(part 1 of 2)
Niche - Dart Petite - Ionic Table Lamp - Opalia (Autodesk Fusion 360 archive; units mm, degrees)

design "Marble Base - Ionic Table Lamp - Ketra Ready - 120V - Opalia Collection" references "Trove - TL", "Arca Tall", "Marble Base - Ionic Table Lamp - Ketra Ready - 120V", "Chinois", "Facet Petite", "Ketra - A20 Tunable Lamp", "Arca Petite", "Orb 8.5In - Solitaire Petite", "Dart Petite", "Dart"
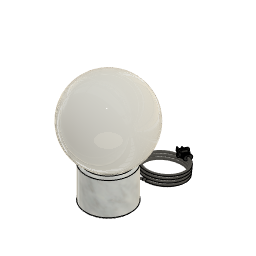
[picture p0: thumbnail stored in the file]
component_insert "Component Insert2"
component_insert "Component Insert3"
component_insert "Component Insert4"
component_insert "Component Insert5"
position "Position1"
component_insert "Component Insert6"
component_insert "Component Insert7"
component_insert "Component Insert8"
external_derived "ExternalDerived1" bodies "Orb-8.5"
derived_instance "DerivedInstance1"
position "Position2"
external_derived "ExternalDerived2" bodies "Dart Grand"
derived_instance "DerivedInstance2"
offset_faces "OffsetFaces1" distance -10.16
position "Position3"
external_derived "ExternalDerived3" bodies "Dart Petite"
derived_instance "DerivedInstance3"
offset_faces "OffsetFaces1" distance -10.16
position "Position4"
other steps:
derived_base_feature "Derived Base Feature1" bodies "Dart Grand"
derived_base_feature "Derived Base Feature1" bodies "Dart Petite"
derived_base_feature "Derived Base Feature1" bodies "Orb-8.5"
create_component "CreateComponent1"
create_component "CreateComponent2"
create_component "CreateComponent3"
named bodies: "Orb-8.5", "Dart Grand", "Dart Petite"

design "Dart Petite"
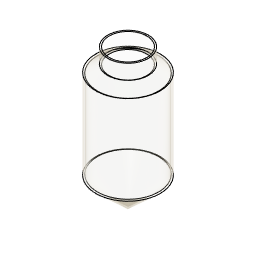
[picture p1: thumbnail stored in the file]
sketch "Sketch1" plane through (0, 0, 0) normal (0, 0, 1) x axis (1, 0, 0)
work_plane "WorkPlane1" AlongDistance 76.2
sketch "Sketch2" plane through (0, 0, 76.2) normal (0, 0, 1) x axis (1, 0, 0)
sketch "Sketch3" plane through (0, 0, 76.2) normal (0, 0, 1) x axis (1, 0, 0)
sketch "Sketch4" plane through (0, 0, 76.2) normal (0, 0, 1) x axis (1, 0, 0)
  circle C1 centre (0, 0) radius 82.55
  point P1 (0, 0)
  point P2 (0, 0)
  coincident P1 P2
  dimension "d2" diameter C1 = 165.1
loft "Loft1" sketch "Sketch4" bodies "Dart Petite"
extrude "Extrude1" add of existing geometry blind 228.6
work_plane "WorkPlane2" AlongDistance 19.05
sketch "Sketch5" plane through (0, 0, 323.85) normal (0, 0, 1) x axis (1, 0, 0)
  circle C1 centre (0, 0) radius 52.07
  point P1 (0, 0)
  point P2 (0, 0)
  coincident P1 P2
  dimension "d6" diameter C1 = 104.14
loft "Loft2" sketch "Sketch5"
extrude "Extrude2" add of existing geometry blind 38.1
shell "Shell3" innerThickness 3.81
component_from_bodies "Body->Comp"
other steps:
base_feature "Base Feature" bodies "Dart Petite"
create_component "CreateComponent1"
remove_body "RemoveBody1"
named bodies: "Dart Petite"

design "Marble Base - Ionic Table Lamp - Ketra Ready - 120V" references "Marble Base - Ionic Table Lamp - 120V"
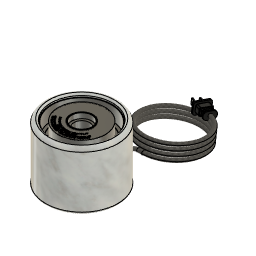
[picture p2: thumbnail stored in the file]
external_derived "ExternalDerived1" bodies "Coiled - SVT (Blk Fabric)", "Body1", "Marble Base", "Body2", "Silicone Gasket", "Plastic Insert"
derived_instance "DerivedInstance1"
derived_instance "DerivedInstance2"
derived_instance "DerivedInstance3"
derived_instance "DerivedInstance4"
derived_instance "DerivedInstance5"
derived_instance "DerivedInstance6"
derived_instance "DerivedInstance7"
derived_instance "DerivedInstance8"
derived_instance "DerivedInstance9"
derived_instance "DerivedInstance10"
derived_instance "DerivedInstance11"
derived_instance "DerivedInstance12"
offset_faces "OffsetFaces1" distance 3.81
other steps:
derived_base_feature "Derived Base Feature1" bodies "Rubber Grommet"
derived_base_feature "Derived Base Feature1" bodies "Neoprene Pad"
derived_base_feature "Derived Base Feature1" bodies "2-Pole Plug End"
derived_base_feature "Derived Base Feature1" bodies "Body1"
derived_base_feature "Derived Base Feature1" bodies "Body1", "Body2"
derived_base_feature "Derived Base Feature1" bodies "Body1"
derived_base_feature "Derived Base Feature1" bodies "Silicone Gasket"
derived_base_feature "Derived Base Feature1" bodies "Plastic Insert"
derived_base_feature "Derived Base Feature1" bodies "Body1"
derived_base_feature "Derived Base Feature1" bodies "Body1"
derived_base_feature "Derived Base Feature1" bodies "Coiled - SVT (Blk Fabric)"
derived_base_feature "Derived Base Feature1" bodies "Marble Base"
create_component "CreateComponent1"
create_component "CreateComponent2"
create_component "CreateComponent3"
create_component "CreateComponent4"
create_component "CreateComponent5"
create_component "CreateComponent6"
create_component "CreateComponent7"
create_component "CreateComponent8"
create_component "CreateComponent9"
create_component "CreateComponent10"
create_component "CreateComponent11"
create_component "CreateComponent12"
named bodies: "Coiled - SVT (Blk Fabric)", "Marble Base", "Body1", "Body2", "Plastic Insert", "Silicone Gasket", "Neoprene Pad", "2-Pole Plug End", "Rubber Grommet"

design "Arca Petite"
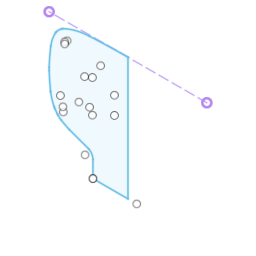
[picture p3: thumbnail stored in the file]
sketch "Sketch1" plane through (0, 0, 0) normal (0, 1, 0) x axis (1, 0, 0)
  line L1 (0, 101.6) -> (0, -101.6)
  line L2 (127, 0) -> (-127, 0)
  line L3 (63.5, 101.6) -> (-63.5, 101.6)
  perpendicular L1 L2
  parallel L2 L3
sketch "Sketch2" plane through (0, 0, 0) normal (0, 1, 0) x axis (1, 0, 0)
  line L1 (0, 101.6) -> (0, -101.6)
  line L2 (0, -76.2) -> (0, 101.6)
  line L3 (127, 0) -> (-127, 0)
  line L4 (114.3, 0) -> (-114.3, 0)
  line L5 (50.8, 101.6) -> (50.8, 63.5)
  line L6 (-50.8, 101.6) -> (50.8, 101.6)
  line L7 (-50.8, 63.5) -> (-50.8, 101.6)
  line L8 (63.5, 101.6) -> (-63.5, 101.6)
  line L9 (114.3, -76.2) -> (114.3, 63.5)
  line L10 (-114.3, -76.2) -> (114.3, -76.2)
  line L11 (-114.3, 63.5) -> (-114.3, -76.2)
  line L12 (-50.8, 63.5) -> (-114.3, 63.5)
  line L13 (114.3, 63.5) -> (50.8, 63.5)
  point P2 (0, 101.6)
  point P5 (0, 101.6)
  point P6 (0, -76.2)
  point P9 (-114.3, 0)
  point P10 (114.3, 0)
  point P11 (50.8, 101.6)
  point P19 (50.8, 63.5)
  coincident P2 P5
  coincident L1 P6
  coincident L3 P9
  coincident L3 P10
  vertical L5
  horizontal L6
  vertical L7
  coincident P11 L8
  horizontal L12
  vertical L9
  horizontal L10
  vertical L11
  coincident P19 L12
  collinear L12 L13
derived_base_feature "Derived Base Feature"
revolve "Revolve1" sketch "Sketch4" AlongAngle 360 bodies "Arca Petite"
shell "Shell1" innerThickness 3.81
component_from_bodies "Body->Comp"
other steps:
base_feature "Base Feature" bodies "Arca Petite"
create_component "CreateComponent1"
remove_body "RemoveBody1"
named bodies: "Arca Petite"

design "Neoprene Pad"
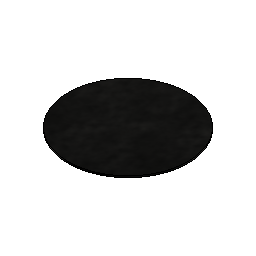
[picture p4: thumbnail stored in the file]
sketch "Sketch1" plane through (0, 0, 0) normal (0, 0, 1) x axis (1, 0, 0)
  circle C1 centre (0, 0) radius 57.15
  point P1 (0, 0)
  point P2 (0, 0)
  coincident P1 P2
extrude "Extrude1" new body sketch "Sketch1" along normal blind 1.5875 bodies "Neoprene Pad"
component_from_bodies "Body->Comp"
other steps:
base_feature "Base Feature" bodies "Neoprene Pad"
create_component "CreateComponent1"
remove_body "RemoveBody1"
named bodies: "Neoprene Pad"

design "T9 - Bulb"
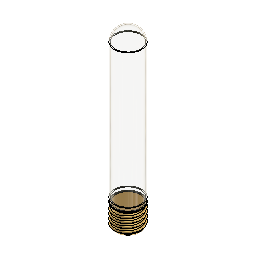
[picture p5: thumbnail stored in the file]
sketch "Sketch1" plane through (0, 0, 0) normal (0, 1, 0) x axis (1, 0, 0)
  line L1 (0, -166.37) -> (0, 0)
  line L2 (13.97, -13.97) -> (13.97, -152.4)
  line L3 (-13.97, -152.4) -> (-13.97, -13.97)
  line L4 (0, 0) -> (0, -166.37)
  line L5 (12.97, -13.97) -> (12.97, -152.4)
  line L6 (-12.97, -152.4) -> (-12.97, -13.97)
  line L7 (-12.3978, -10.16) -> (-13.4404, -10.16)
  line L8 (13.4404, -10.16) -> (12.3978, -10.16)
  arc A1 centre (0, -152.4) radius 13.97 clockwise from (13.97, -152.4) to (-13.97, -152.4)
  arc A2 centre (0, -152.4) radius 12.97 clockwise from (12.97, -152.4) to (-12.97, -152.4)
  arc A3 centre (0, -13.97) radius 13.97 clockwise from (13.4404, -10.16) to (13.97, -13.97)
  arc A4 centre (0, -13.97) radius 13.97 clockwise from (-13.97, -13.97) to (-13.4404, -10.16)
  arc A5 centre (0, -13.97) radius 12.97 clockwise from (12.3978, -10.16) to (12.97, -13.97)
  arc A6 centre (0, -13.97) radius 12.97 clockwise from (-12.97, -13.97) to (-12.3978, -10.16)
  point P1 (0, 0)
  point P2 (0, 0)
  point P3 (0, -166.37)
  point P10 (0, 0)
  point P17 (13.4404, -10.16)
  point P19 (12.3978, -10.16)
  point P4 (13.97, -152.4)
  point P5 (13.97, -13.97)
  coincident P1 P2
  vertical L1
  tangent L2 A3
  tangent L3 A3
  parallel L2 L3
  tangent L3 A1
  tangent L2 A1
  midpoint P3 A1
  coincident P1 P10
  perpendicular L1 L7
  coincident P17 L7
  concentric A3 A4
  coincident P10 A3
  concentric A1 A2
  tangent L5 A2
  tangent L5 A5
  tangent L6 A5
  tangent L6 A2
  coincident P19 L7
  concentric A5 A6
  collinear L7 L8
  dimension "d6" distance L2 L3 = 27.94
  dimension "d7" distance P4 P5 = 138.43
revolve "Revolve1" sketch "Sketch1" AlongAngle 360 bodies "T9"
derived_base_feature "Derived Base Feature" bodies "E26 Base"
align "Align1"
move "Move1"
component_from_bodies "Body->Comp1"
component_from_bodies "Body->Comp2"
copy_paste "CutPaste1"
copy_paste "CutPaste2"
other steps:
base_feature "Base Feature1" bodies "T9"
base_feature "Base Feature1" bodies "E26 Base"
create_component "CreateComponent1"
create_component "CreateComponent2"
remove_body "RemoveBody1"
create_component "CreateComponent3"
remove_body "RemoveBody2"
remove_instance "RemoveInstance1"
remove_instance "RemoveInstance2"
named bodies: "T9", "E26 Base"

design "Facet Petite"
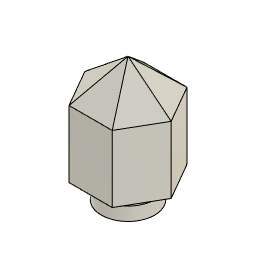
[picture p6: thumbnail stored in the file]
sketch "Sketch7" plane through (0, 0, 0) normal (1, 0, 0) x axis (0, 1, 0)
sketch "Sketch8" plane through (0, 0, 0) normal (0, 0, 1) x axis (1, 0, 0)
  circle C1 centre (0, 0) radius 50.8
  point P1 (0, 0)
  point P2 (0, 0)
  coincident P1 P2
  dimension "d17" diameter C1 = 101.6
extrude "Extrude5" new body sketch "Sketch8" along normal blind 25.4 and against normal blind 25.4
work_plane "WorkPlane1" AlongDistance 17.78
sketch "Sketch10" plane through (0, 0, 25.4) normal (0, 0, 1) x axis (-1, 0, 0)
  circle C1 centre (0, 0) radius 50.8
sketch "Sketch12" plane through (0, 0, 43.18) normal (0, 0, 1) x axis (1, 0, 0)
  line L1 (-82.1223, 0) -> (-41.0612, 71.12)
  line L2 (-41.0612, -71.12) -> (-82.1223, 0)
  line L3 (41.0612, -71.12) -> (-41.0612, -71.12)
  line L4 (82.1223, 0) -> (41.0612, -71.12)
  line L5 (41.0612, 71.12) -> (82.1223, 0)
  line L6 (-41.0612, 71.12) -> (41.0612, 71.12)
  point P1 (0, 0)
  point P8 (0, 0)
  coincident P1 P8
  dimension "d22" distance P8 L6 = 71.12
sketch "Sketch15" plane through (0, 0, 0) normal (0, 1, 0) x axis (1, 0, 0)
  line L1 (53.7365, -21.6801) -> (82.1223, -43.18)
  line L2 (-50.8, -25.4) -> (-82.1223, -43.18)
  point P2 (82.1223, -43.18)
  point P3 (82.1223, -43.18)
  point P5 (-82.1223, -43.18)
  point P7 (-82.1223, -43.18)
  point P6 (-50.8, -25.4)
  point P8 (-50.8, -25.4)
  coincident P2 P3
  coincident P5 P7
  coincident P6 P8
sketch "Sketch17" plane through (0, 0, 25.4) normal (0, 0, 1) x axis (-1, 0, 0)
  line L1 (51.3255, 0) -> (0, 0)
  line L2 (73.3235, 0) -> (0, 0)
  line L3 (-41.0612, -71.12) -> (-25.4, -43.9941)
  line L4 (-36.6617, -63.5) -> (-25.4, -43.9941)
  line L5 (78.4305, 0) -> (0, 0)
  line L6 (41.0612, -71.12) -> (25.4, -43.9941)
  line L7 (25.4, 43.9941) -> (41.0612, 71.12)
  line L8 (73.3235, 0) -> (0, 0)
  line L9 (-25.4, 43.9941) -> (-41.0612, 71.12)
  line L10 (0, 0) -> (0, 0)
  circle C1 centre (0, 0) radius 50.8
  point P1 (0, 0)
  point P4 (0, 0)
  point P2 (-41.0612, -71.12)
  point P6 (-41.0612, -71.12)
  point P3 (0, 0)
  point P7 (0, 0)
  point P9 (-25.4, -43.9941)
  point P12 (41.0612, -71.12)
  point P13 (41.0612, -71.12)
  point P15 (25.4, -43.9941)
  point P16 (41.0612, 71.12)
  point P17 (41.0612, 71.12)
  point P18 (25.4, 43.9941)
  point P19 (-41.0612, 71.12)
  point P20 (-41.0612, 71.12)
  point P21 (0, 0)
  point P23 (-25.4, 43.9941)
  point P25 (0, 0)
  point P24 (0, 0)
  point P26 (0, 0)
  horizontal L1
  coincident P1 P4
  coincident P2 P6
  horizontal L2
  coincident P3 P7
  coincident C1 P9
  coincident P12 P13
  horizontal L5
  coincident C1 P15
  coincident P16 P17
  coincident C1 P18
  coincident P19 P20
  horizontal L8
  coincident P1 P21
  coincident C1 P23
  coincident P1 P25
  coincident P24 P26
extrude "Extrude6" new body sketch "Sketch12" along normal blind 127
work_plane "WorkPlane2" AlongDistance 66.04
sketch "Sketch18" plane through (0, 0, 236.22) normal (0, 0, 1) x axis (1, 0, 0)
  line L1 (41.0612, -71.12) -> (0, 0)
  line L2 (82.1223, 0) -> (0, 0)
  line L3 (41.0612, 71.12) -> (0, 0)
  line L4 (-41.0612, 71.12) -> (0, 0)
  line L5 (-82.1223, 0) -> (0, 0)
  line L6 (-41.0612, -71.12) -> (0, 0)
  point P1 (0, 0)
  point P3 (0, 0)
  point P2 (41.0612, -71.12)
  point P4 (41.0612, -71.12)
  point P6 (0, 0)
  point P5 (82.1223, 0)
  point P7 (82.1223, 0)
  point P9 (0, 0)
  point P8 (41.0612, 71.12)
  point P10 (41.0612, 71.12)
  point P12 (0, 0)
  point P11 (-41.0612, 71.12)
  point P13 (-41.0612, 71.12)
  point P15 (0, 0)
  point P14 (-82.1223, 0)
  point P16 (-82.1223, 0)
  point P18 (0, 0)
  point P17 (-41.0612, -71.12)
  point P19 (-41.0612, -71.12)
  coincident P1 P3
  coincident P2 P4
  coincident P1 P6
  coincident P5 P7
  coincident P1 P9
  coincident P8 P10
  coincident P1 P12
  coincident P11 P13
  coincident P1 P15
  coincident P14 P16
  coincident P1 P18
  coincident P17 P19
loft "Loft1"
loft "Loft2" sketch "Sketch17"
component_from_bodies "Body->Comp"
extrude "Extrude1" cut of existing geometry blind -25.4
shell "Shell2" innerThickness 3.81
fillet "Fillet1" radius 7.62
fillet "Fillet2" radius 6.35
fillet "Fillet3" radius 6.35
fillet "Fillet4" radius 6.35
fillet "Fillet5" radius 6.35
fillet "Fillet6" radius 6.35
fillet "Fillet7" radius 3.81
fillet "Fillet8" radius 6.35
fillet "Fillet9" radius 6.35
fillet "Fillet10" radius 6.35
fillet "Fillet11" radius 6.35
fillet "Fillet12" radius 6.35
fillet "Fillet13" radius 2.286
shell "Shell1" innerThickness 2.54
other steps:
base_feature "Base Feature"
create_component "CreateComponent3"
remove_body "RemoveBody2"

design "Marble Base - Ionic Table Lamp - 120V" references "Dart", "Rubber Grommet", "Marble Base - Plastic Insert", "Chinois", "2-Pole Plug End", "Neoprene Pad", "Marble Base - Silicone Gasket", "Trove - TL", "Dart Petite", "Balon v2", "T9 - Bulb", "Orb 8.5In - Solitaire Petite", "T9-5In", "T8 LED 11", "Arca Tall", "Facet Petite"
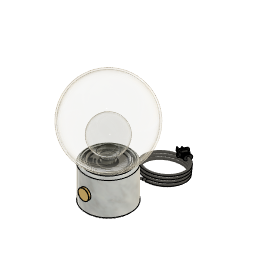
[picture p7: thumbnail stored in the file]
sketch "Sketch1" plane through (0, 0, 0) normal (0, 0, 1) x axis (1, 0, 0)
  circle C1 centre (0, 0) radius 63.5
  point P1 (0, 0)
  point P2 (0, 0)
  coincident P1 P2
extrude "Extrude1" new body sketch "Sketch1" along normal blind 101.6 bodies "Marble Base"
sketch "Sketch2" plane through (0, 0, 101.6) normal (0, 0, 1) x axis (-1, 0, 0)
  circle C1 centre (0, 0) radius 63.5
  circle C2 centre (0, 0) radius 53.975
  concentric C1 C2
  dimension "d3" diameter C2 = 107.95
extrude "Extrude2" cut sketch "Sketch2" profile of C2 against normal blind 34.925
sketch "Sketch3" plane through (0, 0, 66.675) normal (0, 0, 1) x axis (-1, 0, 0)
  circle C1 centre (0, 0) radius 53.975
  circle C2 centre (0, 0) radius 49.276
  point P1 (0, 0)
  point P3 (0, 0)
  coincident P1 P3
  dimension "d6" diameter C2 = 98.552
extrude "Extrude3" cut sketch "Sketch3" profile of C2 against normal blind 45.72
sketch "Sketch4" plane through (0, 0, 0) normal (0, 1, 0) x axis (1, 0, 0)
  circle C1 centre (0, -50.8) radius 3.81
  dimension "d9" diameter C1 = 7.62
extrude "Extrude4" cut sketch "Sketch4" against normal blind 127
sketch "Sketch5" plane through (0, 0, 0) normal (0, 1, 0) x axis (1, 0, 0)
  line L1 (0, -25.4) -> (0, 0)
  line L2 (0, -30.48) -> (0, -25.4)
  circle C1 centre (0, -30.48) radius 5.08
  point P1 (0, 0)
  point P2 (0, 0)
  point P4 (0, -30.48)
  point P5 (0, -30.48)
  coincident P1 P2
  vertical L1
  parallel L1 L2
  coincident P4 P5
  dimension "d12" diameter C1 = 10.16
extrude "Extrude5" cut sketch "Sketch5" profile of C1 along normal blind 114.3
fillet "Fillet1" radius 6.35 3.175 4.064
derived_base_feature "Derived Base Feature1" bodies "Rotary Switch"
derived_base_feature "Derived Base Feature1" bodies "Coiled - SVT (Blk Fabric)"
derived_base_feature "Derived Base Feature1" bodies "Glass Globe"
derived_base_feature "Derived Base Feature1" bodies "Metal Housing"
derived_base_feature "Derived Base Feature1" bodies "Metal Socket Cover"
derived_base_feature "Derived Base Feature1" bodies "Porcelain Socket"
derived_base_feature "Derived Base Feature1" bodies "Brass Dial - Dimmer Knob"
component_from_bodies "Body->Comp1"
offset_faces "OffsetFaces1" distance 12.7
offset_faces "OffsetFaces2" distance -12.7
derived_base_feature "Derived Base Feature1" bodies "Solitaire Petite"
move "Move1"
offset_faces "OffsetFaces1" distance 20.32
move "Move2"
extrude "Extrude6" add of existing geometry blind 25.4
offset_faces "OffsetFaces2" distance -3.81
fillet "Fillet2" radius 2.54
move "Move3"
derived_base_feature "Derived Base Feature2" bodies "Facet Petite"
move "Move4"
offset_faces "OffsetFaces1" distance 2.54
move "Move1"
derived_base_feature "Derived Base Feature1" bodies "Body1"
derived_base_feature "Derived Base Feature1" bodies "Body1"
derived_base_feature "Derived Base Feature1" bodies "Body1"
derived_base_feature "Derived Base Feature1" bodies "Body1"
derived_base_feature "Derived Base Feature1" bodies "Body1"
derived_base_feature "Derived Base Feature1" bodies "Body1", "Body2"
derived_base_feature "Derived Base Feature1" bodies "Body1"
position "Position1"
external_derived "ExternalDerived5" bodies "Plastic Insert"
derived_instance "DerivedInstance15"
offset_faces "OffsetFaces1" distance 3.81
offset_faces "OffsetFaces2" distance -1.0414
move "Move6"
external_derived "ExternalDerived6" sketch "Sketch3" bodies "Silicone Gasket"
derived_instance "DerivedInstance16"
offset_faces "OffsetFaces3" distance -10.795
move "Move1"
move_face "MoveFace1"
position "Position2"
position "Position3"
position "Position4"
position "Position5"
move "Move2"
position "Position6"
offset_faces "OffsetFaces2" distance -7.62
chamfer "Chamfer1" distance 0.381
remove_instance "RemoveInstance1"
remove_instance "RemoveInstance2"
remove_instance "RemoveInstance3"
remove_instance "RemoveInstance4"
move "Move1"
derived_base_feature "Derived Base Feature5" bodies "Oculo Petite"
align "Align1"
external_derived "ExternalDerived8"
derived_base_feature "Derived Base Feature7" bodies "Balon v2"
derived_base_feature "Derived Base Feature8" bodies "Balon v3"
align "Align3"
align "Align4"
external_derived "ExternalDerived10"
component_insert "Component Insert1"
position "Position7"
position "Position8"
derived_base_feature "Derived Base Feature11" bodies "Trove - TL"
move "Move10"
move "Move11"
remove_instance "RemoveInstance5"
split "Split1" bodies "Trove - TL (1)"
remove_body "RemoveBody2"
remove_body "RemoveBody3"
external_derived "ExternalDerived13" bodies "Trove - TL"
derived_instance "DerivedInstance20"
remove_body "RemoveBody4"
remove_body "RemoveBody5"
component_insert "Component Insert2"
component_insert "Component Insert3"
component_from_bodies "Body->Comp2"
remove_body "RemoveBody7"
move "Move12"
move "Move13"
sketch "Sketch6" plane through (0, 0, 97.917) normal (0, 0, 1) x axis (-1, 0, 0)
  circle C1 centre (0, 0) radius 41.275
  circle C2 centre (0, 0) radius 19.685
  arc A1 centre (0, 0) radius 29.3982 clockwise from (-27.6283, 10.0466) to (27.6283, 10.0466)
  arc A2 centre (0, 0) radius 26.2232 clockwise from (-24.6444, 8.9616) to (24.6444, 8.9616)
  arc A3 centre (0, 0) radius 32.5732 clockwise from (-30.6121, 11.1317) to (30.6121, 11.1317)
  arc A4 centre (0, 0) radius 35.7482 clockwise from (-33.596, 12.2167) to (33.596, 12.2167)
  point P1 (0, 0)
  point P3 (0, 0)
  coincident P1 P3
  dimension "d37" = -3.175
  dimension "d38" = 3.175
  dimension "d39" = 6.35
  dimension "d40" Text1-Height = 2.54
  dimension "d41" Text2-Height = 2.54
  dimension "d42" Text3-Height = 2.54
  dimension "d43" Text4-Height = 2.54
extrude "Extrude1" cut sketch "Sketch6" against normal blind 0.254
external_derived "ExternalDerived14" bodies "Rubber Grommet"
derived_instance "DerivedInstance19"
external_derived "ExternalDerived15" bodies "2-Pole Plug End"
derived_instance "DerivedInstance18"
external_derived "ExternalDerived16" bodies "Neoprene Pad"
derived_instance "DerivedInstance17"
position "Position9"
position "Position10"
position "Position11"
position "Position12"
external_derived "ExternalDerived17" bodies "Chinois"
derived_instance "DerivedInstance21"
position "Position13"
move "Move3"
remove_body "RemoveBody8"
component_insert "Component Insert4"
offset_faces "OffsetFaces3" distance 50.8
component_insert "Component Insert5"
position "Position14"
external_derived "ExternalDerived18" bodies "Dart Grand"
derived_instance "DerivedInstance22"
offset_faces "OffsetFaces1" distance -10.16
position "Position15"
external_derived "ExternalDerived19" bodies "Dart Petite"
derived_instance "DerivedInstance23"
offset_faces "OffsetFaces1" distance -10.16
position "Position16"
component_insert "Component Insert6"
position "Position17"
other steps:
derived_base_feature "Derived Base Feature1" bodies "Trove - TL"
derived_base_feature "Derived Base Feature1" bodies "Chinois"
derived_base_feature "Derived Base Feature1" bodies "Dart Grand"
derived_base_feature "Derived Base Feature1" bodies "Dart Petite"
derived_base_feature "Derived Base Feature1" bodies "Rubber Grommet"
derived_base_feature "Derived Base Feature1" bodies "Neoprene Pad"
derived_base_feature "Derived Base Feature1" bodies "2-Pole Plug End"
move "Move1"
derived_base_feature "Derived Base Feature1" bodies "Plastic Insert"
derived_base_feature "Derived Base Feature1" bodies "Silicone Gasket"
base_feature "Base Feature1" bodies "Oculo Petite", "Arca Petite"
base_feature "Base Feature1" bodies "Marble Base"
move "Move8"
derived_base_feature "Derived Base Feature"
create_component "CreateComponent1"
create_component "CreateComponent2"
create_component "CreateComponent3"
create_component "CreateComponent4"
create_component "CreateComponent5"
create_component "CreateComponent6"
create_component "CreateComponent7"
create_component "CreateComponent8"
remove_body "RemoveBody1"
create_component "CreateComponent9"
create_component "CreateComponent10"
create_component "CreateComponent11"
create_component "CreateComponent12"
create_component "CreateComponent13"
create_component "CreateComponent14"
create_component "CreateComponent15"
create_component "CreateComponent16"
create_component "CreateComponent17"
create_component "CreateComponent18"
remove_body "RemoveBody6"
create_component "CreateComponent19"
create_component "CreateComponent20"
create_component "CreateComponent21"
create_component "CreateComponent22"
create_component "CreateComponent23"
create_component "CreateComponent24"
create_component "CreateComponent25"
named bodies: "Marble Base", "Rotary Switch", "Coiled - SVT (Blk Fabric)", "Glass Globe", "Metal Housing", "Metal Socket Cover", "Porcelain Socket", "Brass Dial - Dimmer Knob", "Solitaire Petite", "Facet Petite", "Body1", "Body2", "Plastic Insert", "Silicone Gasket", "Oculo Petite", "Balon v2", "Balon v3", "Trove - TL", "Trove - TL (1)", "Arca Petite", "Neoprene Pad", "2-Pole Plug End", "Rubber Grommet", "Chinois", "Dart Grand", "Dart Petite"

design "Marble Base - Silicone Gasket"
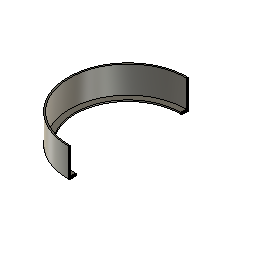
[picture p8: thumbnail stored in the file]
sketch "Sketch1" plane through (0, 0, 0) normal (0, 0, 1) x axis (1, 0, 0)
  circle C1 centre (0, 0) radius 53.34
  point P1 (0, 0)
  point P2 (0, 0)
  coincident P1 P2
extrude "Extrude1" new body sketch "Sketch1" along normal blind 25.4 bodies "Silicone Gasket"
shell "Shell1" innerThickness 1.27
sketch "Sketch2" plane through (0, 0, 1.27) normal (0, 0, 1) x axis (-1, 0, 0)
  circle C1 centre (0, 0) radius 52.07
  circle C2 centre (0, 0) radius 46.99
  concentric C1 C2
extrude "Extrude2" cut sketch "Sketch2" profile of C2 against normal blind 12.7
component_from_bodies "Body->Comp"
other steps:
base_feature "Base Feature" bodies "Silicone Gasket"
create_component "CreateComponent1"
remove_body "RemoveBody1"
named bodies: "Silicone Gasket"

design "Balon v2"
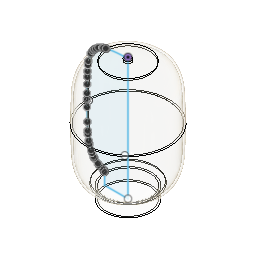
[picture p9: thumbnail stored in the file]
derived_base_feature "Derived Base Feature" bodies "Balon"
work_plane "WorkPlane1" AlongDistance 0
sketch "Sketch1" plane through (0, 0, 0) normal (0, 1, 0) x axis (1, 0, 0)
  line L1 (0, 317.5) -> (0, 2.9083)
  curve K1 (-82.9821, 124.2212) -> (-50.8, 237.8015)
  curve K2 (-51.0925, 237.681) -> (-50.8, 237.8015)
  curve K3 (-51.3855, 237.5558) -> (-51.0925, 237.681)
  curve K4 (-54.7608, 236.0513) -> (-51.3855, 237.5558)
  curve K5 (-57.9615, 234.05) -> (-54.7608, 236.0513)
  curve K6 (-67.2727, 226.749) -> (-57.9615, 234.05)
  curve K7 (-69.0552, 224.2615) -> (-67.2727, 226.749)
  curve K8 (-72.1872, 218.7832) -> (-69.0552, 224.2615)
  curve K9 (-74.1213, 215.1556) -> (-72.1872, 218.7832)
  curve K10 (-78.3031, 204.3965) -> (-74.1213, 215.1556)
  curve K11 (-79.7275, 197.3397) -> (-78.3031, 204.3965)
  curve K12 (-81.3333, 185.4664) -> (-79.7275, 197.3397)
  curve K13 (-81.6254, 178.4008) -> (-81.3333, 185.4664)
  curve K14 (-82.49, 152.2133) -> (-81.6254, 178.4008)
  curve K15 (-82.9821, 136.067) -> (-82.49, 152.2133)
  curve K16 (-82.9821, 124.2212) -> (-82.9821, 136.067)
  curve K17 (50.8, 237.7999) -> (82.9821, 124.2212)
  curve K18 (82.9821, 140.3031) -> (82.9821, 124.2212)
  curve K19 (81.9353, 169.4257) -> (82.9821, 140.3031)
  curve K20 (81.3621, 183.6489) -> (81.9353, 169.4257)
  curve K21 (80.9478, 189.8724) -> (81.3621, 183.6489)
  curve K22 (77.8147, 206.9858) -> (80.9478, 189.8724)
  curve K23 (74.9652, 213.2153) -> (77.8147, 206.9858)
  curve K24 (69.4688, 224.1531) -> (74.9652, 213.2153)
  curve K25 (67.2512, 226.458) -> (69.4688, 224.1531)
  curve K26 (61.5696, 231.3138) -> (67.2512, 226.458)
  curve K27 (57.377, 234.6711) -> (61.5696, 231.3138)
  curve K28 (52.0556, 237.2628) -> (57.377, 234.6711)
  curve K29 (51.4313, 237.5413) -> (52.0556, 237.2628)
  curve K30 (50.8, 237.7999) -> (51.4313, 237.5413)
  line L2 (-50.8, 317.5) -> (-50.8, 237.8015)
  line L3 (50.8, 317.5) -> (50.8, 237.7999)
  line L4 (-19.0713, 6.7501) -> (-19.0713, 6.7501)
  curve K31 (82.9821, 124.1958) -> (40.1509, 7.3012)
  curve K32 (41.8198, 7.6176) -> (40.1509, 7.3012)
  curve K33 (43.2113, 8.0663) -> (41.8198, 7.6176)
  curve K34 (47.0139, 9.2854) -> (43.2113, 8.0663)
  curve K35 (47.3314, 9.3805) -> (47.0139, 9.2854)
  curve K36 (50.1192, 10.3272) -> (47.3314, 9.3805)
  curve K37 (51.833, 11.0085) -> (50.1192, 10.3272)
  curve K38 (57.8313, 14.1895) -> (51.833, 11.0085)
  curve K39 (61.4491, 17.0488) -> (57.8313, 14.1895)
  curve K40 (66.8203, 21.5867) -> (61.4491, 17.0488)
  curve K41 (68.5372, 23.5528) -> (66.8203, 21.5867)
  curve K42 (71.2201, 27.8971) -> (68.5372, 23.5528)
  curve K43 (74.7424, 33.8984) -> (71.2201, 27.8971)
  curve K44 (78.2342, 44.8406) -> (74.7424, 33.8984)
  curve K45 (79.6792, 50.3463) -> (78.2342, 44.8406)
  curve K46 (81.3558, 63.5576) -> (79.6792, 50.3463)
  curve K47 (81.6386, 70.4415) -> (81.3558, 63.5576)
  curve K48 (82.4897, 96.2198) -> (81.6386, 70.4415)
  curve K49 (82.9814, 112.3523) -> (82.4897, 96.2198)
  curve K50 (82.9821, 124.1958) -> (82.9814, 112.3523)
  curve K51 (-40.1501, 7.301) -> (-82.9821, 124.1958)
  curve K52 (-82.9813, 110.5256) -> (-82.9821, 124.1958)
  curve K53 (-82.2545, 88.8594) -> (-82.9813, 110.5256)
  curve K54 (-81.6277, 70.519) -> (-82.2545, 88.8594)
  curve K55 (-81.3572, 64.3441) -> (-81.6277, 70.519)
  curve K56 (-79.4149, 46.8924) -> (-81.3572, 64.3441)
  curve K57 (-76.5204, 38.9768) -> (-79.4149, 46.8924)
  curve K58 (-73.5142, 32.2947) -> (-76.5204, 38.9768)
  curve K59 (-72.5556, 30.3818) -> (-73.5142, 32.2947)
  curve K60 (-69.7914, 25.3691) -> (-72.5556, 30.3818)
  curve K61 (-68.3824, 23.4028) -> (-69.7914, 25.3691)
  curve K62 (-64.5419, 19.5456) -> (-68.3824, 23.4028)
  curve K63 (-62.3002, 17.7646) -> (-64.5419, 19.5456)
  curve K64 (-53.6583, 11.1976) -> (-62.3002, 17.7646)
  curve K65 (-49.6968, 10.1396) -> (-53.6583, 11.1976)
  curve K66 (-43.4141, 8.1331) -> (-49.6968, 10.1396)
  curve K67 (-41.9704, 7.6516) -> (-43.4141, 8.1331)
  curve K68 (-40.1963, 7.3098) -> (-41.9704, 7.6516)
  curve K69 (-40.1732, 7.3054) -> (-40.1963, 7.3098)
  curve K70 (-40.1501, 7.301) -> (-40.1732, 7.3054)
  line L5 (-82.9821, 124.1958) -> (-82.9821, 124.2212)
  line L6 (82.9821, 124.2212) -> (82.9821, 124.1958)
  line L7 (0, 317.5) -> (-50.8, 317.5)
  line L8 (7.2015, 3.048) -> (0, 3.048)
  line L9 (0, 3.048) -> (-7.2015, 3.048)
  arc A1 centre (0, 188.595) radius 185.6867 clockwise from (-7.2015, 3.048) to (-40.1502, 7.301)
  arc A2 centre (0, 188.595) radius 185.6867 clockwise from (40.151, 7.3012) to (7.2015, 3.048)
  point P38 (-40.1502, 7.301)
  point P43 (40.1509, 7.3012)
  point P62 (-40.1501, 7.301)
  point P81 (40.151, 7.3012)
  point P84 (0, 3.048)
  vertical L1
  horizontal L4
  coincident P38 K51
  symmetric L1 A1 A2
  coincident A2 P43
  coincident A1 P62
  coincident K31 P81
  perpendicular L2 L7
  horizontal L8
  coincident L1 P84
  horizontal L9
revolve "Revolve1" sketch "Sketch1" AlongAngle 360
shell "Shell1" innerThickness 3.81
fillet "Fillet1" radius 6.35
offset_faces "OffsetFaces1" distance -50.8
move "Move1"
move "Move2"
component_from_bodies "Body->Comp1"
component_from_bodies "Body->Comp2"
sketch "Sketch2" plane through (0, 0, 0) normal (0, 1, 0) x axis (1, 0, 0)
  line L1 (-85.5221, 124.2212) -> (-85.5221, 124.1961)
  curve K1 (-58.9057, 236.4383) -> (-50.8, 241.7989)
  curve K2 (-50.8, 241.554) -> (-50.8, 241.7989)
  curve K3 (-50.904, 240.933) -> (-50.8, 241.554)
  curve K4 (-51.2936, 240.2837) -> (-50.904, 240.933)
  curve K5 (-51.734, 239.7561) -> (-51.2936, 240.2837)
  curve K6 (-53.328, 238.5038) -> (-51.734, 239.7561)
  curve K7 (-54.0892, 238.1997) -> (-53.328, 238.5038)
  curve K8 (-58.9057, 236.4383) -> (-54.0892, 238.1997)
  curve K9 (-89.3309, 124.2212) -> (-58.9057, 236.4383)
  curve K10 (-62.6336, 234.9735) -> (-58.9057, 236.4383)
  curve K11 (-65.581, 233.1032) -> (-62.6336, 234.9735)
  curve K12 (-73.0224, 227.0019) -> (-65.581, 233.1032)
  curve K13 (-74.8981, 224.836) -> (-73.0224, 227.0019)
  curve K14 (-78.1104, 219.6097) -> (-74.8981, 224.836)
  curve K15 (-80.2663, 215.561) -> (-78.1104, 219.6097)
  curve K16 (-84.0943, 205.8277) -> (-80.2663, 215.561)
  curve K17 (-85.4655, 200.1154) -> (-84.0943, 205.8277)
  curve K18 (-87.4092, 188.5789) -> (-85.4655, 200.1154)
  curve K19 (-87.7349, 182.3889) -> (-87.4092, 188.5789)
  curve K20 (-88.4233, 165.9645) -> (-87.7349, 182.3889)
  curve K21 (-89.328, 138.6964) -> (-88.4233, 165.9645)
  curve K22 (-89.3309, 124.2212) -> (-89.328, 138.6964)
  line L2 (-89.3309, 124.1958) -> (-89.3309, 124.2212)
  curve K23 (-46.5001, 7.301) -> (-89.3309, 124.1958)
  curve K24 (-89.3314, 112.4293) -> (-89.3309, 124.1958)
  curve K25 (-88.8181, 95.3068) -> (-89.3314, 112.4293)
  curve K26 (-88.346, 81.2892) -> (-88.8181, 95.3068)
  curve K27 (-88.0298, 70.4902) -> (-88.346, 81.2892)
  curve K28 (-87.1514, 58.328) -> (-88.0298, 70.4902)
  curve K29 (-86.3326, 50.6119) -> (-87.1514, 58.328)
  curve K30 (-81.0932, 33.6688) -> (-86.3326, 50.6119)
  curve K31 (-77.3163, 27.4309) -> (-81.0932, 33.6688)
  curve K32 (-74.8955, 23.6666) -> (-77.3163, 27.4309)
  curve K33 (-73.5108, 22.0741) -> (-74.8955, 23.6666)
  curve K34 (-70.2346, 19.0457) -> (-73.5108, 22.0741)
  curve K35 (-64.8094, 14.3548) -> (-70.2346, 19.0457)
  curve K36 (-56.6696, 10.3041) -> (-64.8094, 14.3548)
  curve K37 (-54.0053, 9.483) -> (-56.6696, 10.3041)
  curve K38 (-49.1487, 7.9411) -> (-54.0053, 9.483)
  curve K39 (-48.3482, 7.6526) -> (-49.1487, 7.9411)
  curve K40 (-46.5001, 7.301) -> (-48.3482, 7.6526)
  line L3 (0, 266.7) -> (0, 0)
  line L4 (0, 3.048) -> (-7.7894, 3.048)
  line L5 (-50.8, 266.7) -> (-50.8, 241.7989)
  line L6 (0, 266.7) -> (-50.8, 266.7)
  arc A1 centre (-6.9779, 188.7329) radius 185.6867 clockwise from (-7.7894, 3.048) to (-46.5001, 7.301)
  point P1 (0, 0)
  point P44 (0, 0)
  point P46 (0, 3.048)
  point P5 (-50.8, 241.554)
  point P49 (0, 266.7)
  coincident P1 P44
  coincident L3 P46
  coincident P5 L5
  coincident L3 P49
revolve "Revolve2" sketch "Sketch2" AlongAngle 360 bodies "Balon v3"
shell "Shell2" innerThickness 3.81
component_from_bodies "Body->Comp3"
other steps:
base_feature "Base Feature1" bodies "Balon"
base_feature "Base Feature1" bodies "Balon v3"
base_feature "Base Feature1" bodies "Balon v2"
create_component "CreateComponent1"
remove_body "RemoveBody1"
create_component "CreateComponent2"
remove_body "RemoveBody2"
create_component "CreateComponent3"
remove_body "RemoveBody3"
named bodies: "Balon", "Balon v2", "Balon v3"

design "Arca Tall"
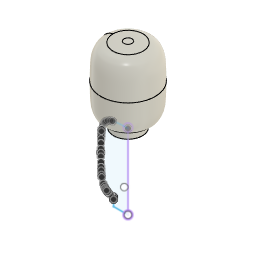
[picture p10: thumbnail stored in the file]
derived_base_feature "Derived Base Feature" bodies "Balon"
work_plane "WorkPlane1" AlongDistance 0
sketch "Sketch1" plane through (0, 0, 0) normal (0, 1, 0) x axis (1, 0, 0)
  line L1 (0, 317.5) -> (0, 2.9083)
  curve K1 (-82.9821, 124.2212) -> (-50.8, 237.8015)
  curve K2 (-51.0925, 237.681) -> (-50.8, 237.8015)
  curve K3 (-51.3855, 237.5558) -> (-51.0925, 237.681)
  curve K4 (-54.7608, 236.0513) -> (-51.3855, 237.5558)
  curve K5 (-57.9615, 234.05) -> (-54.7608, 236.0513)
  curve K6 (-67.2727, 226.749) -> (-57.9615, 234.05)
  curve K7 (-69.0552, 224.2615) -> (-67.2727, 226.749)
  curve K8 (-72.1872, 218.7832) -> (-69.0552, 224.2615)
  curve K9 (-74.1213, 215.1556) -> (-72.1872, 218.7832)
  curve K10 (-78.3031, 204.3965) -> (-74.1213, 215.1556)
  curve K11 (-79.7275, 197.3397) -> (-78.3031, 204.3965)
  curve K12 (-81.3333, 185.4664) -> (-79.7275, 197.3397)
  curve K13 (-81.6254, 178.4008) -> (-81.3333, 185.4664)
  curve K14 (-82.49, 152.2133) -> (-81.6254, 178.4008)
  curve K15 (-82.9821, 136.067) -> (-82.49, 152.2133)
  curve K16 (-82.9821, 124.2212) -> (-82.9821, 136.067)
  curve K17 (50.8, 237.7999) -> (82.9821, 124.2212)
  curve K18 (82.9821, 140.3031) -> (82.9821, 124.2212)
  curve K19 (81.9353, 169.4257) -> (82.9821, 140.3031)
  curve K20 (81.3621, 183.6489) -> (81.9353, 169.4257)
  curve K21 (80.9478, 189.8724) -> (81.3621, 183.6489)
  curve K22 (77.8147, 206.9858) -> (80.9478, 189.8724)
  curve K23 (74.9652, 213.2153) -> (77.8147, 206.9858)
  curve K24 (69.4688, 224.1531) -> (74.9652, 213.2153)
  curve K25 (67.2512, 226.458) -> (69.4688, 224.1531)
  curve K26 (61.5696, 231.3138) -> (67.2512, 226.458)
  curve K27 (57.377, 234.6711) -> (61.5696, 231.3138)
  curve K28 (52.0556, 237.2628) -> (57.377, 234.6711)
  curve K29 (51.4313, 237.5413) -> (52.0556, 237.2628)
  curve K30 (50.8, 237.7999) -> (51.4313, 237.5413)
  line L2 (-50.8, 317.5) -> (-50.8, 237.8015)
  line L3 (50.8, 317.5) -> (50.8, 237.7999)
  line L4 (-19.0713, 6.7501) -> (-19.0713, 6.7501)
  curve K31 (82.9821, 124.1958) -> (40.1509, 7.3012)
  curve K32 (41.8198, 7.6176) -> (40.1509, 7.3012)
  curve K33 (43.2113, 8.0663) -> (41.8198, 7.6176)
  curve K34 (47.0139, 9.2854) -> (43.2113, 8.0663)
  curve K35 (47.3314, 9.3805) -> (47.0139, 9.2854)
  curve K36 (50.1192, 10.3272) -> (47.3314, 9.3805)
  curve K37 (51.833, 11.0085) -> (50.1192, 10.3272)
  curve K38 (57.8313, 14.1895) -> (51.833, 11.0085)
  curve K39 (61.4491, 17.0488) -> (57.8313, 14.1895)
  curve K40 (66.8203, 21.5867) -> (61.4491, 17.0488)
  curve K41 (68.5372, 23.5528) -> (66.8203, 21.5867)
  curve K42 (71.2201, 27.8971) -> (68.5372, 23.5528)
  curve K43 (74.7424, 33.8984) -> (71.2201, 27.8971)
  curve K44 (78.2342, 44.8406) -> (74.7424, 33.8984)
  curve K45 (79.6792, 50.3463) -> (78.2342, 44.8406)
  curve K46 (81.3558, 63.5576) -> (79.6792, 50.3463)
  curve K47 (81.6386, 70.4415) -> (81.3558, 63.5576)
  curve K48 (82.4897, 96.2198) -> (81.6386, 70.4415)
  curve K49 (82.9814, 112.3523) -> (82.4897, 96.2198)
  curve K50 (82.9821, 124.1958) -> (82.9814, 112.3523)
  curve K51 (-40.1501, 7.301) -> (-82.9821, 124.1958)
  curve K52 (-82.9813, 110.5256) -> (-82.9821, 124.1958)
  curve K53 (-82.2545, 88.8594) -> (-82.9813, 110.5256)
  curve K54 (-81.6277, 70.519) -> (-82.2545, 88.8594)
  curve K55 (-81.3572, 64.3441) -> (-81.6277, 70.519)
  curve K56 (-79.4149, 46.8924) -> (-81.3572, 64.3441)
  curve K57 (-76.5204, 38.9768) -> (-79.4149, 46.8924)
  curve K58 (-73.5142, 32.2947) -> (-76.5204, 38.9768)
  curve K59 (-72.5556, 30.3818) -> (-73.5142, 32.2947)
  curve K60 (-69.7914, 25.3691) -> (-72.5556, 30.3818)
  curve K61 (-68.3824, 23.4028) -> (-69.7914, 25.3691)
  curve K62 (-64.5419, 19.5456) -> (-68.3824, 23.4028)
  curve K63 (-62.3002, 17.7646) -> (-64.5419, 19.5456)
  curve K64 (-53.6583, 11.1976) -> (-62.3002, 17.7646)
  curve K65 (-49.6968, 10.1396) -> (-53.6583, 11.1976)
  curve K66 (-43.4141, 8.1331) -> (-49.6968, 10.1396)
  curve K67 (-41.9704, 7.6516) -> (-43.4141, 8.1331)
  curve K68 (-40.1963, 7.3098) -> (-41.9704, 7.6516)
  curve K69 (-40.1732, 7.3054) -> (-40.1963, 7.3098)
  curve K70 (-40.1501, 7.301) -> (-40.1732, 7.3054)
  line L5 (-82.9821, 124.1958) -> (-82.9821, 124.2212)
  line L6 (82.9821, 124.2212) -> (82.9821, 124.1958)
  line L7 (0, 317.5) -> (-50.8, 317.5)
  line L8 (7.2015, 3.048) -> (0, 3.048)
  line L9 (0, 3.048) -> (-7.2015, 3.048)
  arc A1 centre (0, 188.595) radius 185.6867 clockwise from (-7.2015, 3.048) to (-40.1502, 7.301)
  arc A2 centre (0, 188.595) radius 185.6867 clockwise from (40.151, 7.3012) to (7.2015, 3.048)
  point P38 (-40.1502, 7.301)
  point P43 (40.1509, 7.3012)
  point P62 (-40.1501, 7.301)
  point P81 (40.151, 7.3012)
  point P84 (0, 3.048)
  vertical L1
  horizontal L4
  coincident P38 K51
  symmetric L1 A1 A2
  coincident A2 P43
  coincident A1 P62
  coincident K31 P81
  perpendicular L2 L7
  horizontal L8
  coincident L1 P84
  horizontal L9
revolve "Revolve1" sketch "Sketch1" AlongAngle 360
shell "Shell1" innerThickness 3.81
fillet "Fillet1" radius 6.35 bodies "Balon v3"
offset_faces "OffsetFaces1" distance -50.8
move "Move1"
move "Move2"
component_from_bodies "Body->Comp1"
component_from_bodies "Body->Comp2"
sketch "Sketch2" plane through (0, 0, 0) normal (0, 1, 0) x axis (1, 0, 0)
  line L1 (-85.5221, 124.2212) -> (-85.5221, 124.1961)
  curve K1 (-58.9057, 236.4383) -> (-50.8, 241.7989)
  curve K2 (-50.8, 241.554) -> (-50.8, 241.7989)
  curve K3 (-50.904, 240.933) -> (-50.8, 241.554)
  curve K4 (-51.2936, 240.2837) -> (-50.904, 240.933)
  curve K5 (-51.734, 239.7561) -> (-51.2936, 240.2837)
  curve K6 (-53.328, 238.5038) -> (-51.734, 239.7561)
  curve K7 (-54.0892, 238.1997) -> (-53.328, 238.5038)
  curve K8 (-58.9057, 236.4383) -> (-54.0892, 238.1997)
  curve K9 (-89.3309, 124.2212) -> (-58.9057, 236.4383)
  curve K10 (-62.6336, 234.9735) -> (-58.9057, 236.4383)
  curve K11 (-65.581, 233.1032) -> (-62.6336, 234.9735)
  curve K12 (-73.0224, 227.0019) -> (-65.581, 233.1032)
  curve K13 (-74.8981, 224.836) -> (-73.0224, 227.0019)
  curve K14 (-78.1104, 219.6097) -> (-74.8981, 224.836)
  curve K15 (-80.2663, 215.561) -> (-78.1104, 219.6097)
  curve K16 (-84.0943, 205.8277) -> (-80.2663, 215.561)
  curve K17 (-85.4655, 200.1154) -> (-84.0943, 205.8277)
  curve K18 (-87.4092, 188.5789) -> (-85.4655, 200.1154)
  curve K19 (-87.7349, 182.3889) -> (-87.4092, 188.5789)
  curve K20 (-88.4233, 165.9645) -> (-87.7349, 182.3889)
  curve K21 (-89.328, 138.6964) -> (-88.4233, 165.9645)
  curve K22 (-89.3309, 124.2212) -> (-89.328, 138.6964)
  line L2 (-89.3309, 124.1958) -> (-89.3309, 124.2212)
  curve K23 (-46.5001, 7.301) -> (-89.3309, 124.1958)
  curve K24 (-89.3314, 112.4293) -> (-89.3309, 124.1958)
  curve K25 (-88.8181, 95.3068) -> (-89.3314, 112.4293)
  curve K26 (-88.346, 81.2892) -> (-88.8181, 95.3068)
  curve K27 (-88.0298, 70.4902) -> (-88.346, 81.2892)
  curve K28 (-87.1514, 58.328) -> (-88.0298, 70.4902)
  curve K29 (-86.3326, 50.6119) -> (-87.1514, 58.328)
  curve K30 (-81.0932, 33.6688) -> (-86.3326, 50.6119)
  curve K31 (-77.3163, 27.4309) -> (-81.0932, 33.6688)
  curve K32 (-74.8955, 23.6666) -> (-77.3163, 27.4309)
  curve K33 (-73.5108, 22.0741) -> (-74.8955, 23.6666)
  curve K34 (-70.2346, 19.0457) -> (-73.5108, 22.0741)
  curve K35 (-64.8094, 14.3548) -> (-70.2346, 19.0457)
  curve K36 (-56.6696, 10.3041) -> (-64.8094, 14.3548)
  curve K37 (-54.0053, 9.483) -> (-56.6696, 10.3041)
  curve K38 (-49.1487, 7.9411) -> (-54.0053, 9.483)
  curve K39 (-48.3482, 7.6526) -> (-49.1487, 7.9411)
  curve K40 (-46.5001, 7.301) -> (-48.3482, 7.6526)
  line L3 (0, 266.7) -> (0, 0)
  line L4 (0, 3.048) -> (-7.7894, 3.048)
  line L5 (-50.8, 266.7) -> (-50.8, 241.7989)
  line L6 (0, 266.7) -> (-50.8, 266.7)
  arc A1 centre (-6.9779, 188.7329) radius 185.6867 clockwise from (-7.7894, 3.048) to (-46.5001, 7.301)
  point P1 (0, 0)
  point P44 (0, 0)
  point P46 (0, 3.048)
  point P5 (-50.8, 241.554)
  point P49 (0, 266.7)
  coincident P1 P44
  coincident L3 P46
  coincident P5 L5
  coincident L3 P49
revolve "Revolve2" sketch "Sketch2" AlongAngle 360 bodies "Balon v3"
shell "Shell2" innerThickness 3.81
component_from_bodies "Body->Comp3"
remove_instance "RemoveInstance1"
remove_instance "RemoveInstance2"
sketch "Sketch1" plane through (0, 0, 0) normal (0, 1, 0) x axis (1, 0, 0)
  line L1 (-6.35, 3.048) -> (-14.1394, 3.048)
  curve K1 (-52.8501, 7.301) -> (-95.6809, 124.1958)
  curve K2 (-95.6814, 112.4293) -> (-95.6809, 124.1958)
  curve K3 (-95.1681, 95.3068) -> (-95.6814, 112.4293)
  curve K4 (-94.696, 81.2892) -> (-95.1681, 95.3068)
  curve K5 (-94.3798, 70.4902) -> (-94.696, 81.2892)
  curve K6 (-93.5014, 58.328) -> (-94.3798, 70.4902)
  curve K7 (-92.6826, 50.6119) -> (-93.5014, 58.328)
  curve K8 (-87.4432, 33.6688) -> (-92.6826, 50.6119)
  curve K9 (-83.6663, 27.4309) -> (-87.4432, 33.6688)
  curve K10 (-81.2455, 23.6666) -> (-83.6663, 27.4309)
  curve K11 (-79.8608, 22.0741) -> (-81.2455, 23.6666)
  curve K12 (-76.5846, 19.0457) -> (-79.8608, 22.0741)
  curve K13 (-71.12, 13.97) -> (-76.5846, 19.0457)
  curve K14 (-62.23, 10.16) -> (-71.12, 13.97)
  curve K15 (-60.3553, 9.483) -> (-62.23, 10.16)
  curve K16 (-55.4987, 7.9411) -> (-60.3553, 9.483)
  curve K17 (-54.6982, 7.6526) -> (-55.4987, 7.9411)
  curve K18 (-52.8501, 7.301) -> (-54.6982, 7.6526)
  line L2 (-95.6809, 124.1958) -> (-95.6809, 124.2212)
  line L3 (0, 266.7) -> (0, 0)
  line L4 (0, 3.048) -> (-6.35, 3.048)
  line L5 (-95.6809, 124.2466) -> (-95.6809, 124.2212)
  line L6 (-50.8, 266.7) -> (-50.8, 241.7989)
  line L7 (0, 266.7) -> (-50.8, 266.7)
  curve K19 (-71.6837, 232.5587) -> (-50.8, 241.7989)
  curve K20 (-50.8, 237.8015) -> (-50.8, 241.7989)
  curve K21 (-53.6019, 236.5654) -> (-50.8, 237.8015)
  curve K22 (-59.7861, 236.0598) -> (-53.6019, 236.5654)
  curve K23 (-64.4375, 235.2772) -> (-59.7861, 236.0598)
  curve K24 (-69.8917, 233.4707) -> (-64.4375, 235.2772)
  curve K25 (-71.6837, 232.5587) -> (-69.8917, 233.4707)
  curve K26 (-71.6837, 232.5587) -> (-95.6809, 124.2466)
  curve K27 (-95.6814, 136.0132) -> (-95.6809, 124.2466)
  curve K28 (-95.1681, 153.1357) -> (-95.6814, 136.0132)
  curve K29 (-94.696, 167.1533) -> (-95.1681, 153.1357)
  curve K30 (-94.3798, 177.9523) -> (-94.696, 167.1533)
  curve K31 (-93.5014, 190.1145) -> (-94.3798, 177.9523)
  curve K32 (-92.6826, 197.8306) -> (-93.5014, 190.1145)
  curve K33 (-87.4432, 214.7737) -> (-92.6826, 197.8306)
  curve K34 (-83.6663, 221.0115) -> (-87.4432, 214.7737)
  curve K35 (-81.2455, 224.7759) -> (-83.6663, 221.0115)
  curve K36 (-79.8608, 226.3684) -> (-81.2455, 224.7759)
  curve K37 (-77.083, 228.9361) -> (-79.8608, 226.3684)
  curve K38 (-75.5537, 230.2778) -> (-77.083, 228.9361)
  curve K39 (-71.6837, 232.5587) -> (-75.5537, 230.2778)
  curve K40 (-50.8, 244.8458) -> (-50.8, 244.8469)
  curve K41 (-50.8, 244.8465) -> (-50.8, 244.8469)
  curve K42 (-50.8, 244.8462) -> (-50.8, 244.8465)
  curve K43 (-50.8, 244.8458) -> (-50.8, 244.8462)
  arc A1 centre (-13.3279, 188.7329) radius 185.6867 clockwise from (-14.1394, 3.048) to (-52.8501, 7.301)
  point P26 (0, 3.048)
  point P33 (-50.8, 237.8015)
  point P35 (-50.8, 237.8015)
  point P40 (-71.6837, 232.5587)
  point P53 (-50.8, 244.8458)
  coincident L3 P26
  perpendicular L3 L4
  coincident P33 P35
  coincident K19 P40
  coincident L6 P53
sketch "Sketch2" plane through (0, 0, 0) normal (0, 1, 0) x axis (1, 0, 0)
  line L1 (-95.6809, 124.1958) -> (-95.6809, 124.2212)
  line L2 (0, 266.7) -> (-50.8, 266.7)
  curve K1 (-58.9317, 239.3909) -> (-50.8, 244.8469)
  curve K2 (-50.8, 244.602) -> (-50.8, 244.8469)
  curve K3 (-50.904, 243.981) -> (-50.8, 244.602)
  curve K4 (-51.2936, 243.3317) -> (-50.904, 243.981)
  curve K5 (-51.734, 242.8041) -> (-51.2936, 243.3317)
  curve K6 (-53.328, 241.5518) -> (-51.734, 242.8041)
  curve K7 (-54.0892, 241.2477) -> (-53.328, 241.5518)
  curve K8 (-58.9317, 239.3909) -> (-54.0892, 241.2477)
  line L3 (-50.8, 266.7) -> (-50.8, 244.8458)
  curve K9 (-52.8501, 7.301) -> (-95.6809, 124.1958)
  curve K10 (-95.6814, 112.4293) -> (-95.6809, 124.1958)
  curve K11 (-95.1681, 95.3068) -> (-95.6814, 112.4293)
  curve K12 (-94.696, 81.2892) -> (-95.1681, 95.3068)
  curve K13 (-94.3798, 70.4902) -> (-94.696, 81.2892)
  curve K14 (-93.5014, 58.328) -> (-94.3798, 70.4902)
  curve K15 (-92.6826, 50.6119) -> (-93.5014, 58.328)
  curve K16 (-87.4432, 33.6688) -> (-92.6826, 50.6119)
  curve K17 (-83.6663, 27.4309) -> (-87.4432, 33.6688)
  curve K18 (-81.2455, 23.6666) -> (-83.6663, 27.4309)
  curve K19 (-79.8608, 22.0741) -> (-81.2455, 23.6666)
  curve K20 (-76.5846, 19.0457) -> (-79.8608, 22.0741)
  curve K21 (-73.7599, 16.6033) -> (-76.5846, 19.0457)
  curve K22 (-65.532, 11.7145) -> (-73.7599, 16.6033)
  curve K23 (-60.3553, 9.483) -> (-65.532, 11.7145)
  curve K24 (-55.4987, 7.9411) -> (-60.3553, 9.483)
  curve K25 (-54.6982, 7.6526) -> (-55.4987, 7.9411)
  curve K26 (-52.8501, 7.301) -> (-54.6982, 7.6526)
  line L4 (-95.6809, 124.2466) -> (-95.6809, 124.2212)
  line L5 (0, 3.048) -> (-6.35, 3.048)
  line L6 (-6.35, 3.048) -> (-14.1394, 3.048)
  curve K27 (-58.9317, 239.3909) -> (-95.6809, 124.2466)
  curve K28 (-95.6814, 136.0132) -> (-95.6809, 124.2466)
  curve K29 (-95.1681, 153.1357) -> (-95.6814, 136.0132)
  curve K30 (-94.696, 167.1533) -> (-95.1681, 153.1357)
  curve K31 (-94.3798, 177.9523) -> (-94.696, 167.1533)
  curve K32 (-93.5014, 190.1145) -> (-94.3798, 177.9523)
  curve K33 (-92.6826, 197.8306) -> (-93.5014, 190.1145)
  curve K34 (-87.4432, 214.7737) -> (-92.6826, 197.8306)
  curve K35 (-83.6663, 221.0115) -> (-87.4432, 214.7737)
  curve K36 (-81.2455, 224.7759) -> (-83.6663, 221.0115)
  curve K37 (-79.8608, 226.3684) -> (-81.2455, 224.7759)
  curve K38 (-76.5846, 229.3968) -> (-79.8608, 226.3684)
  curve K39 (-73.7599, 231.8391) -> (-76.5846, 229.3968)
  curve K40 (-65.833, 236.5491) -> (-73.7599, 231.8391)
  curve K41 (-61.4585, 238.4785) -> (-65.833, 236.5491)
  curve K42 (-58.9317, 239.3909) -> (-61.4585, 238.4785)
  line L7 (0, 3.048) -> (0, 266.7)
  arc A1 centre (-13.3279, 188.7329) radius 185.6867 clockwise from (-14.1394, 3.048) to (-52.8501, 7.301)
  point P52 (-50.8, 244.8458)
  coincident K1 P52
  perpendicular L5 L7
revolve "Revolve1" sketch "Sketch1" AlongAngle 360 bodies "Balon v3.3"
shell "Shell1" innerThickness 3.81
revolve "Revolve2" sketch "Sketch2" AlongAngle 360 bodies "Balon v3.2"
shell "Shell2" innerThickness 3.81
component_from_bodies "Body->Comp1"
component_from_bodies "Body->Comp2"
position "Position1"
remove_instance "RemoveInstance1" bodies "Balon v3"
remove_instance "RemoveInstance2"
move "Move1"
position "Position2" bodies "Balon v3"
sketch "Sketch3" plane through (0, 0, 0) normal (0, 1, 0) x axis (1, 0, 0)
  line L1 (0, 50.8) -> (0, -304.8)
  line L2 (127, 50.8) -> (127, -304.8)
  line L3 (-127, 50.8) -> (-127, -304.8)
  line L4 (139.7, 25.4) -> (-139.7, 25.4)
  line L5 (139.7, -292.1) -> (-139.7, -292.1)
  line L6 (95.25, 50.8) -> (95.25, -304.8)
  vertical L1
  dimension "d6" = 127
  dimension "d12" = -127
  dimension "d17" distance L4 L5 = 317.5
  dimension "d18" = 95.25
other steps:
base_feature "Base Feature1" bodies "Balon v3.3"
base_feature "Base Feature1" bodies "Balon v3.2"
base_feature "Base Feature1" bodies "Balon"
base_feature "Base Feature1" bodies "Balon v3"
base_feature "Base Feature1" bodies "Balon v2"
create_component "CreateComponent1"
remove_body "RemoveBody1"
create_component "CreateComponent2"
remove_body "RemoveBody2"
create_component "CreateComponent3"
remove_body "RemoveBody3" bodies "Balon v3"
create_component "CreateComponent1"
create_component "CreateComponent2"
remove_body "RemoveBody1" bodies "Balon v3"
create_component "CreateComponent3"
remove_body "RemoveBody2" bodies "Balon v3"
named bodies: "Balon", "Balon v2", "Balon v3", "Balon v3.3", "Balon v3.2"

design "T8 LED 11" references "T9 - Bulb"
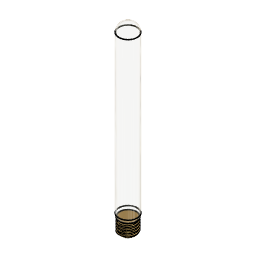
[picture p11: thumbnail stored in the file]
sketch "Sketch1" plane through (0, 0, 0) normal (0, 0, 1) x axis (1, 0, 0)
  circle C1 centre (0, 0) radius 14.986
  point P1 (0, 0)
  point P2 (0, 0)
  coincident P1 P2
  dimension "d1" diameter C1 = 29.972
sketch "Sketch2" plane through (0, 0, 0) normal (0, 1, 0) x axis (1, 0, 0)
  line L1 (0, -273.05) -> (0, 2.54)
  line L2 (15.24, -2.54) -> (15.24, -257.81)
  line L3 (-15.24, -257.81) -> (-15.24, -2.54)
  line L4 (0, 12.7) -> (0, -273.05)
  line L5 (-15.24, 2.54) -> (15.24, 2.54)
  arc A1 centre (0, -2.54) radius 15.24 clockwise from (-15.24, -2.54) to (15.24, -2.54)
  arc A2 centre (0, -257.81) radius 15.24 clockwise from (15.24, -257.81) to (-15.24, -257.81)
  point P2 (0, -273.05)
  point P9 (0, 12.7)
  point P12 (0, 2.54)
  point P1 (0, 0)
  vertical L1
  tangent L2 A1
  tangent A1 L3
  parallel L2 L3
  tangent L3 A2
  tangent L2 A2
  midpoint P2 A2
  midpoint A1 P9
  parallel L1 L4
  horizontal L5
  coincident L5 P12
  dimension "d2" distance P1 P2 = 273.05
revolve "Revolve1" sketch "Sketch2" AlongAngle 360
shell "Shell1" innerThickness 0.9906
external_derived "ExternalDerived1" bodies "E26 Base"
align "Align1"
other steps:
